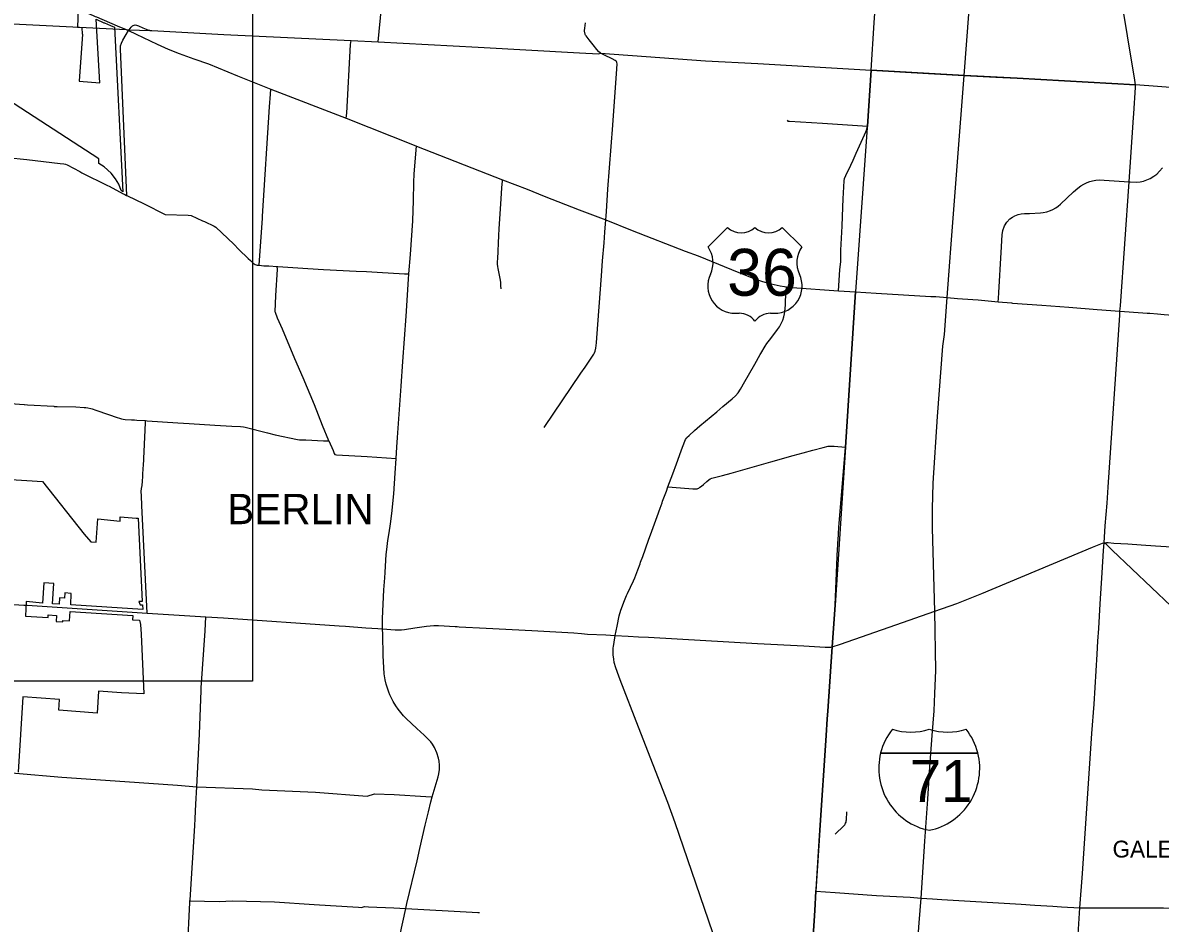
# Model space of a CAD drawing. Extents: x 1729596 to 1925846, y 659247 to 911751.
# Drawn here: x 1821771 to 1855559, y 807237 to 833985 of the extents above; entities that cross this region are included whole.
import ezdxf

# ---------------------------------------------------------------- set-up
doc = ezdxf.new("R2010")
doc.units = 0
for name, color, linetype in [('GM_X_City_Street', 7, 'Continuous'), ('GM_X_Corporation', 7, 'Continuous'), ('GM_X_Corporation_Text', 7, 'Continuous'), ('GM_X_County_Road', 7, 'Continuous'), ('GM_X_Interstate_Route', 7, 'Continuous'), ('GM_X_Interstate_Shield', 7, 'Continuous'), ('GM_X_Township', 7, 'Continuous'), ('GM_X_Township_Road', 7, 'Continuous'), ('GM_X_Township_Text', 7, 'Continuous'), ('GM_X_US_Route', 7, 'Continuous'), ('GM_X_US_Shield', 7, 'Continuous'), ('SH_Data', 7, 'Continuous')]:
    doc.layers.add(name, color=color, linetype=linetype)

msp = doc.modelspace()

# ---------------------------------------------------------------- linework, layer by layer
at = {"layer": 'GM_X_City_Street'}
msp.add_lwpolyline([(1819183, 816827), (1819368, 816835), (1819716, 816815), (1819794, 816805), (1820031, 816793), (1820776, 816743), (1820982, 816713), (1821507, 816705), (1821800, 816689)], dxfattribs=at)
at = {"layer": 'GM_X_Corporation'}
for points in [[(1823415, 834383), (1823397, 833851), (1823528, 833845), (1823535, 833649), (1823542, 833643), (1823444, 832245), (1824058, 832202), (1823955, 834094), (1824182, 833983), (1824200, 833986), (1824290, 833942), (1824382, 833903), (1824500, 833849), (1824747, 828967), (1824696, 828999), (1824623, 829186), (1824531, 829351), (1824401, 829520), (1824191, 829701), (1824029, 829809), (1824031, 829939), (1819982, 832569)], [(1821268, 820431), (1822355, 820361), (1823597, 818799), (1823790, 818570), (1823953, 818559), (1824004, 819253), (1824662, 819185), (1824669, 819305), (1825142, 819273), (1825203, 819269), (1825322, 816796), (1825222, 816791), (1825257, 816693), (1825327, 816696), (1825334, 816556), (1823195, 816692), (1823214, 817036), (1823021, 817048), (1823013, 816898), (1822864, 816908), (1822854, 816713), (1822655, 816726), (1822693, 817326), (1822394, 817345), (1822356, 816745), (1821876, 816790), (1821850, 816358), (1822524, 816314), (1822529, 816396), (1822775, 816380), (1822764, 816201), (1822961, 816188), (1822964, 816233), (1823161, 816221), (1823178, 816495), (1825044, 816377), (1825036, 816251), (1825240, 816235), (1825272, 816107), (1825289, 815828), (1825372, 814048), (1824702, 814085), (1824021, 814132), (1823980, 813477), (1822844, 813570), (1822863, 813884), (1821774, 813966), (1821636, 811724)]]:
    msp.add_lwpolyline(points, dxfattribs=at)
at = {"layer": 'GM_X_County_Road'}
for points in [[(1846971, 832575), (1846971, 832575), (1847065, 833986), (1848030, 848046), (1848128, 849585)], [(1854821, 832136), (1854806, 832276), (1853927, 837618), (1853916, 837681), (1853270, 841855), (1853135, 842607), (1853071, 843001), (1853019, 843312), (1852359, 847640), (1852342, 847746)], [(1838934, 833082), (1838875, 833130), (1838820, 833190), (1838713, 833324), (1838593, 833477), (1838502, 833596), (1838490, 833616), (1838481, 833634), (1838474, 833652), (1838468, 833671), (1838464, 833691), (1838461, 833711), (1838461, 833751), (1838466, 833825), (1838487, 833985)], [(1839405, 832831), (1839399, 832841), (1839368, 832866), (1839279, 832914), (1839055, 833020), (1838934, 833082)], [(1839090, 828131), (1839096, 828247), (1839106, 828377), (1839155, 829045), (1839297, 830940), (1839419, 832616), (1839427, 832761), (1839419, 832807), (1839405, 832831)], [(1846005, 826026), (1846043, 826645), (1846071, 826890), (1846074, 827230), (1846113, 827938), (1846126, 828505), (1846142, 828753), (1846166, 829288), (1846184, 829357), (1846219, 829446), (1846366, 829753), (1846439, 829908), (1846529, 830116), (1846779, 830659), (1846815, 830740), (1846834, 830797), (1846854, 830870), (1846863, 830918), (1846971, 832575)], [(1854753, 831025), (1854754, 831032), (1854771, 831285), (1854824, 832063), (1854821, 832136)], [(1854354, 825422), (1854377, 825574), (1854631, 829258), (1854753, 831025)], [(1834143, 812015), (1834139, 812054), (1834124, 812138), (1834075, 812302), (1834002, 812457), (1833942, 812552), (1833889, 812623), (1833831, 812690), (1833694, 812820), (1833478, 813020), (1833162, 813314), (1833078, 813403), (1832999, 813495), (1832925, 813592), (1832856, 813693), (1832774, 813828), (1832679, 814020), (1832645, 814102), (1832604, 814215), (1832566, 814343), (1832538, 814463), (1832516, 814584), (1832508, 814645), (1832492, 814829), (1832476, 815177), (1832464, 815817), (1832460, 815979), (1832454, 816292), (1832494, 817138), (1832523, 817499), (1832533, 817655), (1832557, 818019), (1832570, 818189), (1832583, 818334), (1832618, 818604), (1832651, 818829), (1832693, 819102), (1832736, 819407), (1832789, 819993), (1832829, 820607), (1832863, 821044), (1832886, 821374), (1832904, 821666), (1833012, 823190), (1833063, 823927), (1833158, 825274), (1833233, 826364), (1833244, 826526), (1833284, 827097), (1833354, 828099), (1833377, 828710), (1833389, 829242), (1833401, 829499), (1833463, 830322)], [(1850745, 825700), (1850750, 825794), (1850761, 825975), (1850834, 827165), (1850866, 827684), (1850884, 827817), (1850934, 827955), (1851000, 828061), (1851089, 828156), (1851167, 828213), (1851241, 828254), (1851342, 828291), (1851425, 828309), (1851528, 828316), (1851677, 828322), (1851998, 828336), (1852079, 828347), (1852187, 828372), (1852301, 828412), (1852366, 828442), (1852454, 828491), (1852522, 828537), (1852593, 828595), (1852985, 828961), (1853110, 829075), (1853198, 829141), (1853285, 829192), (1853384, 829239), (1853471, 829269), (1853550, 829290), (1853650, 829307), (1853759, 829315), (1853892, 829310), (1854631, 829258)], [(1837255, 821964), (1838352, 823573), (1838477, 823753), (1838734, 824138), (1838754, 824176), (1838776, 824230), (1838797, 824315), (1838813, 824478), (1838822, 824624), (1838961, 826468), (1838996, 826913), (1839038, 827452), (1839065, 827768), (1839090, 828131)], [(1844428, 825666), (1844430, 825701), (1844439, 825894), (1844455, 826141)], [(1843676, 824135), (1843691, 824163), (1843825, 824382), (1843877, 824459), (1843910, 824506), (1843948, 824557), (1844017, 824645), (1844192, 824870), (1844248, 824955), (1844313, 825075), (1844345, 825149), (1844376, 825251), (1844395, 825340), (1844404, 825395), (1844424, 825605), (1844428, 825666)], [(1853892, 818538), (1853927, 819045), (1853979, 819713), (1854011, 820193), (1854357, 825298), (1854354, 825422)], [(1840108, 817915), (1840125, 817960), (1840185, 818129), (1840360, 818619), (1840456, 818888), (1840615, 819321), (1840707, 819568), (1840763, 819722), (1840773, 819774), (1840889, 820072), (1840934, 820196), (1841077, 820583), (1841186, 820882), (1841282, 821134), (1841343, 821301), (1841435, 821553), (1841459, 821602), (1841482, 821642), (1841498, 821666), (1841562, 821727), (1841728, 821872), (1841885, 822009), (1842387, 822426), (1842567, 822583), (1842842, 822816), (1842945, 822908), (1843026, 822996), (1843091, 823097), (1843134, 823175), (1843183, 823260), (1843512, 823845), (1843676, 824135)], [(1821138, 822696), (1821809, 822641), (1821822, 822641), (1821912, 822636), (1822690, 822592), (1822708, 822591), (1822793, 822586), (1823349, 822572), (1823598, 822559), (1823641, 822554), (1823701, 822546), (1823794, 822525), (1823833, 822514), (1823943, 822480), (1824317, 822351), (1824572, 822264), (1824650, 822239), (1824703, 822223), (1824754, 822212), (1824817, 822203), (1825000, 822190), (1825095, 822188), (1825160, 822183)], [(1825160, 822183), (1825395, 822168), (1825420, 822166), (1825468, 822164), (1826380, 822102), (1826713, 822081), (1827481, 822035), (1827979, 822005), (1828241, 821988), (1828328, 821980), (1828376, 821970), (1829043, 821807), (1829269, 821745), (1829930, 821604), (1829991, 821596), (1830183, 821593), (1830707, 821568), (1830861, 821562), (1830987, 821277), (1831021, 821195), (1831043, 821164), (1831094, 821154), (1832000, 821097), (1832863, 821044)], [(1825464, 816451), (1825308, 819646), (1825294, 819934), (1825289, 820059), (1825298, 820149), (1825316, 820244), (1825321, 820280), (1825325, 820329), (1825352, 820760), (1825357, 820824), (1825422, 822106), (1825420, 822166)], [(1845813, 815443), (1846057, 815523), (1847704, 816100), (1848860, 816509), (1849512, 816739), (1849867, 816870), (1850255, 817032), (1853548, 818404), (1853845, 818524), (1853892, 818538)], [(1852972, 804706), (1852981, 804856), (1853110, 806745), (1853175, 807697), (1853246, 808714), (1853530, 812876), (1853592, 813742), (1853681, 815234), (1853705, 815613), (1853731, 815995), (1853772, 816725), (1853832, 817646), (1853875, 818312), (1853892, 818538)], [(1853892, 818538), (1853963, 818545), (1854011, 818543), (1854178, 818529), (1854595, 818503), (1854991, 818481), (1855415, 818448), (1856692, 818365)], [(1857182, 815299), (1857153, 815378), (1857124, 815436), (1857089, 815491), (1857039, 815553), (1856865, 815727), (1856650, 815933), (1856316, 816250), (1855886, 816655), (1854135, 818318), (1853948, 818496), (1853892, 818538)], [(1839372, 815780), (1839425, 816059), (1839488, 816370), (1839533, 816537), (1839646, 816828), (1839707, 816968), (1839735, 817030), (1839908, 817404), (1839909, 817406), (1839949, 817498), (1840041, 817739), (1840108, 817915)], [(1821800, 816689), (1821867, 816685), (1821902, 816683), (1822499, 816646), (1823384, 816589), (1825464, 816451)], [(1825464, 816451), (1827210, 816341), (1827734, 816305), (1831166, 816072), (1831357, 816058), (1831958, 816015)], [(1831958, 816015), (1832323, 815989), (1832460, 815979), (1832837, 815953), (1832930, 815950), (1833024, 815953), (1833112, 815962), (1833413, 816008), (1833762, 816064), (1833870, 816076), (1833979, 816082), (1834125, 816080), (1834617, 816051), (1834676, 816048), (1834735, 816046), (1835535, 816000), (1836888, 815933), (1838141, 815859), (1838366, 815848), (1838544, 815828), (1839093, 815806), (1839372, 815780)], [(1842846, 805301), (1842837, 805328), (1842772, 805518), (1842519, 806229), (1841146, 810217), (1840928, 810827), (1840065, 813066), (1839518, 814468), (1839479, 814577), (1839387, 814825), (1839342, 814985), (1839324, 815084), (1839310, 815214), (1839307, 815315), (1839311, 815371), (1839312, 815408), (1839319, 815463), (1839325, 815513), (1839372, 815780)], [(1839372, 815780), (1839750, 815761), (1840057, 815746), (1840358, 815730), (1843594, 815549), (1844974, 815476), (1845607, 815434), (1845771, 815433), (1845813, 815443)], [(1833929, 810990), (1834110, 811586), (1834129, 811671), (1834146, 811800), (1834150, 811909), (1834147, 811973), (1834143, 812015)], [(1818834, 811875), (1818898, 811871), (1820200, 811779), (1821551, 811700), (1822928, 811578), (1824804, 811444), (1826371, 811335), (1826943, 811293), (1828599, 811230), (1828871, 811205), (1830463, 811131), (1832006, 811013), (1832221, 811077), (1832807, 811061), (1833745, 811003), (1833929, 810990)], [(1833153, 807676), (1833153, 807676), (1833183, 807819), (1833482, 809095), (1833563, 809462), (1833726, 810146), (1833823, 810547), (1833891, 810845), (1833929, 810990)], [(1832766, 805999), (1832958, 806827), (1832968, 806868), (1833153, 807676)]]:
    msp.add_lwpolyline(points, dxfattribs=at)
at = {"layer": 'GM_X_Interstate_Route'}
for points in [[(1849232, 825823), (1849312, 826884), (1849342, 827283), (1849536, 829857), (1849737, 832422), (1849949, 835289), (1849960, 835440)], [(1848231, 804991), (1848401, 807248), (1848453, 807987), (1848565, 809674), (1848656, 810925), (1848716, 811884), (1848786, 812818), (1848839, 813548), (1848865, 814059), (1848894, 814749), (1848860, 816509), (1848794, 818972), (1848791, 819542), (1848815, 820309), (1848943, 822290), (1849103, 824378), (1849147, 824725), (1849232, 825823)]]:
    msp.add_lwpolyline(points, dxfattribs=at)
at = {"layer": 'GM_X_Interstate_Shield'}
for p, q in [((1847254, 812294), (1850140, 812294)), ((1850140, 812294), (1847254, 812294)), ((1850140, 812294), (1847254, 812294)), ((1847254, 812294), (1850140, 812294)), ((1850140, 812294), (1847254, 812294)), ((1850140, 812294), (1847254, 812294))]:
    msp.add_line(p, q, dxfattribs=at)
for centre, start, end in [((1849072, 811835), 141.669, 165.8066), ((1849072, 811835), 141.669, 165.8066), ((1848149, 814791), 253.0091, 286.9909), ((1848149, 814791), 253.0091, 286.9909), ((1849245, 814791), 253.0091, 286.9909), ((1849245, 814791), 253.0091, 286.9909), ((1848322, 811835), 14.1934, 38.331), ((1848322, 811835), 14.1934, 38.331), ((1849072, 811835), 165.8066, 258.463), ((1849072, 811835), 165.8066, 258.463), ((1848322, 811835), 281.537, 14.1934), ((1848322, 811835), 281.537, 14.1934)]:
    msp.add_arc(centre, 1875, start, end, dxfattribs=at)
at = {"layer": 'GM_X_Township'}
for points in [[(1858606, 831851), (1854821, 832136), (1851310, 832334), (1849737, 832422), (1846971, 832575), (1847065, 833986), (1848030, 848046), (1848128, 849585), (1848752, 859146), (1850615, 859080), (1861827, 858324)], [(1820873, 833984), (1824840, 833781), (1824931, 833776), (1825545, 833759), (1825602, 833752), (1827748, 833636), (1831529, 833453), (1832327, 833414), (1835297, 833263), (1838313, 833094), (1838887, 833066), (1838934, 833082), (1842052, 832856), (1843609, 832772), (1846971, 832575), (1846863, 830918), (1846854, 830870), (1846509, 825988), (1846205, 821378), (1845900, 816686), (1845813, 815443), (1845687, 813540), (1845670, 813309), (1845637, 812811), (1845452, 810003), (1845333, 808188), (1845296, 807619), (1845145, 805182)]]:
    msp.add_lwpolyline(points, dxfattribs=at)
at = {"layer": 'GM_X_Township_Road'}
for points in [[(1832327, 833414), (1832426, 834435), (1832607, 835575), (1832687, 836093), (1832759, 836431), (1832731, 836526), (1832414, 837215), (1832308, 837446), (1832207, 837647)], [(1824911, 833750), (1824931, 833776), (1824988, 833851), (1825028, 833889), (1825051, 833904), (1825079, 833915), (1825108, 833920), (1825149, 833917), (1825208, 833895), (1825339, 833834), (1825392, 833810), (1825482, 833777), (1825540, 833760)], [(1824865, 828850), (1824672, 833200), (1824677, 833301), (1824702, 833383), (1824742, 833469), (1824845, 833635), (1824911, 833750)], [(1825540, 833760), (1825545, 833759), (1825602, 833752), (1827748, 833636), (1831529, 833453), (1832327, 833414)], [(1831379, 831146), (1831397, 831297), (1831511, 833337), (1831529, 833453)], [(1832327, 833414), (1835297, 833263), (1838313, 833094), (1838887, 833066), (1838934, 833082)], [(1846971, 832575), (1848673, 832481)], [(1848673, 832481), (1849737, 832422), (1850671, 832370)], [(1850671, 832370), (1851310, 832334), (1854821, 832136)], [(1828797, 826781), (1828889, 828182), (1828892, 828243), (1829101, 831483), (1829126, 831863), (1829142, 832016)], [(1844480, 831093), (1844497, 831060), (1844550, 831060), (1845524, 831004), (1846863, 830918)], [(1820010, 830806), (1820042, 830778), (1820145, 830662), (1820205, 830609), (1820524, 830257), (1820580, 830196), (1820656, 830123), (1820728, 830055), (1820936, 830023), (1821010, 830011), (1821798, 829929), (1821888, 829919), (1822885, 829807), (1822989, 829796), (1823040, 829782), (1823095, 829767), (1823466, 829565), (1823529, 829531), (1824286, 829155), (1824340, 829128), (1824755, 828908)], [(1854631, 829258), (1854661, 829256), (1854846, 829249), (1854959, 829261), (1855061, 829283), (1855161, 829315), (1855264, 829362), (1855369, 829424), (1855456, 829490), (1855539, 829573), (1855621, 829675)], [(1835977, 826077), (1835975, 826171), (1835970, 826275), (1835952, 826385), (1835926, 826541), (1835897, 826684), (1835886, 826742), (1835877, 826818), (1835875, 826895), (1835879, 826972), (1835915, 827662), (1835926, 827862), (1835981, 828758), (1836002, 829086), (1836021, 829286), (1836024, 829315)], [(1824755, 828908), (1824759, 828906), (1824806, 828881), (1824854, 828855), (1824865, 828850), (1825377, 828604), (1825454, 828567), (1825926, 828329), (1825999, 828292), (1826685, 828268), (1826777, 828264), (1827111, 828106), (1827169, 828078), (1827454, 827939), (1827508, 827913), (1828046, 827407), (1828188, 827254), (1828471, 826984), (1828536, 826919), (1828620, 826843), (1828679, 826807), (1828738, 826785), (1828797, 826781)], [(1828797, 826781), (1828937, 826768), (1829083, 826761), (1829333, 826743), (1829347, 826742)], [(1830861, 821562), (1830675, 822019), (1830437, 822637), (1830098, 823434), (1829858, 824006), (1829489, 824884), (1829338, 825214), (1829276, 825381), (1829272, 825394), (1829293, 825885), (1829337, 826657), (1829333, 826743)], [(1829347, 826742), (1830237, 826689), (1830706, 826659), (1831679, 826611), (1831985, 826593), (1832295, 826575), (1833106, 826529), (1833244, 826526)], [(1846205, 821378), (1846509, 825988)], [(1840934, 820196), (1841554, 820152), (1841675, 820144), (1841771, 820139), (1841789, 820141), (1841806, 820145), (1841824, 820150), (1841857, 820165), (1841886, 820186), (1841932, 820222), (1841987, 820273), (1842088, 820362), (1842150, 820411), (1842188, 820437), (1842243, 820457), (1842436, 820506), (1842558, 820533), (1842815, 820608), (1843441, 820786), (1843996, 820944), (1844660, 821131), (1844951, 821209), (1845239, 821285), (1845542, 821368), (1845693, 821404), (1845774, 821406), (1845873, 821404), (1846205, 821378)], [(1845813, 815443), (1845900, 816686), (1845973, 818365), (1845978, 818443), (1845984, 818548), (1845988, 818619), (1846010, 818988), (1846205, 821378)], [(1826943, 811293), (1827025, 812853), (1827068, 814151), (1827071, 814228), (1827188, 815919), (1827210, 816341)], [(1845336, 808240), (1845452, 810003), (1845637, 812811), (1845670, 813309), (1845687, 813540), (1845813, 815443)], [(1826634, 806376), (1826663, 806429), (1826736, 807853), (1826739, 807902), (1826741, 807936), (1826878, 810126), (1826891, 810353), (1826913, 810774), (1826943, 811293)], [(1845901, 809883), (1846157, 810131), (1846187, 810162), (1846202, 810185), (1846214, 810206), (1846226, 810238), (1846229, 810261), (1846233, 810284), (1846236, 810308), (1846248, 810548)], [(1845145, 805182), (1845296, 807619), (1845333, 808188), (1845336, 808240)], [(1826739, 807902), (1827610, 807886), (1828001, 807902), (1829252, 807875), (1830428, 807799), (1830917, 807766), (1831747, 807711), (1831834, 807709), (1831924, 807730), (1832046, 807721), (1832789, 807693), (1833153, 807676), (1835124, 807566), (1835293, 807558), (1835306, 807557), (1835338, 807552)], [(1845333, 808188), (1845902, 808151), (1847128, 808058), (1847922, 808022), (1848130, 808008), (1848453, 807987), (1848798, 807964), (1849069, 807946), (1851423, 807800), (1851838, 807775), (1852372, 807742), (1852621, 807728), (1853175, 807697)], [(1853175, 807697), (1854218, 807699), (1855651, 807697), (1856991, 807682), (1857244, 807678), (1857423, 807675), (1857597, 807668)]]:
    msp.add_lwpolyline(points, dxfattribs=at)
at = {"layer": 'GM_X_US_Route'}
for points in [[(1823602, 834310), (1823863, 834198), (1823927, 834172), (1823961, 834158), (1824572, 833896)], [(1824572, 833896), (1824840, 833781), (1824911, 833750), (1825142, 833644), (1825759, 833347), (1826092, 833198), (1826420, 833073), (1826849, 832915), (1827284, 832761), (1828153, 832411), (1829142, 832016), (1831379, 831146), (1833393, 830350), (1833463, 830322), (1836024, 829315), (1836751, 829041), (1837258, 828837), (1838300, 828432), (1839090, 828131), (1839877, 827816), (1841448, 827196), (1841834, 827061), (1842819, 826655), (1843343, 826451), (1843520, 826379), (1843742, 826300), (1843999, 826225), (1844265, 826170), (1844402, 826149)], [(1844402, 826149), (1844455, 826141), (1844585, 826124), (1844623, 826121), (1846005, 826026), (1846509, 825988)], [(1846509, 825988), (1847116, 825949), (1848742, 825856), (1848890, 825849), (1849232, 825823)], [(1849232, 825823), (1849538, 825792), (1849689, 825784)], [(1849689, 825784), (1850151, 825758), (1850745, 825700), (1851142, 825661), (1851169, 825659)], [(1851169, 825659), (1852041, 825594), (1852847, 825534), (1853684, 825470), (1854354, 825422), (1855037, 825370)], [(1855037, 825370), (1855173, 825360), (1855248, 825354), (1855476, 825337), (1855674, 825320), (1855808, 825306), (1855988, 825281), (1856219, 825240), (1856454, 825186), (1856610, 825146), (1856879, 825067), (1857093, 824992), (1857448, 824848), (1857746, 824717), (1857872, 824661)]]:
    msp.add_lwpolyline(points, dxfattribs=at)
at = {"layer": 'GM_X_US_Shield'}
for p, q in [((1842708, 827907), (1842128, 827327)), ((1842708, 827907), (1842128, 827327)), ((1844912, 827327), (1844332, 827907)), ((1844912, 827327), (1844332, 827907)), ((1842940, 825355), (1843056, 825355)), ((1842940, 825355), (1843056, 825355)), ((1843984, 825355), (1844100, 825355)), ((1843984, 825355), (1844100, 825355))]:
    msp.add_line(p, q, dxfattribs=at)
for centre, radius, start, end in [((1843114, 828322), 580, 225.573, 314.427), ((1843114, 828322), 580, 225.573, 314.427), ((1843926, 828322), 580, 225.573, 314.427), ((1843926, 828322), 580, 225.573, 314.427), ((1841463, 826861), 812, 334.5471, 35.0009), ((1841463, 826861), 812, 334.5471, 35.0009), ((1845578, 826861), 812, 144.9991, 205.4529), ((1845578, 826861), 812, 144.9991, 205.4529), ((1842931, 826167), 812, 154.8319, 270.6383), ((1842931, 826167), 812, 154.8319, 270.6383), ((1844109, 826167), 812, 269.3617, 25.1681), ((1844109, 826167), 812, 269.3617, 25.1681), ((1843056, 824775), 580, 36.8699, 90), ((1843056, 824775), 580, 36.8699, 90), ((1843984, 824775), 580, 90, 143.1301), ((1843984, 824775), 580, 90, 143.1301)]:
    msp.add_arc(centre, radius, start, end, dxfattribs=at)
at = {"layer": 'SH_Data'}
for p, q in [((1828599, 890928), (1828599, 814428)), ((1828599, 814428), (1752099, 814428))]:
    msp.add_line(p, q, dxfattribs=at)

# ---------------------------------------------------------------- texts
at = {"layer": 'GM_X_Corporation_Text'}
msp.add_text('GALENA', height=500, rotation=0, dxfattribs=at).set_placement((1854142, 809190))
at = {"layer": 'GM_X_Interstate_Shield'}
msp.add_text('71', height=1250, dxfattribs=at).set_placement((1848119, 810841))
msp.add_text('71', height=1250, dxfattribs=at).set_placement((1848119, 810841))
at = {"layer": 'GM_X_Township_Text'}
msp.add_text('BERLIN', height=900, rotation=0, dxfattribs=at).set_placement((1827845, 819091))
at = {"layer": 'GM_X_US_Shield'}
msp.add_text('36', height=1392.2, dxfattribs=at).set_placement((1842693, 825877))
msp.add_text('36', height=1392.2, dxfattribs=at).set_placement((1842693, 825877))

doc.saveas('drawing.dxf')
